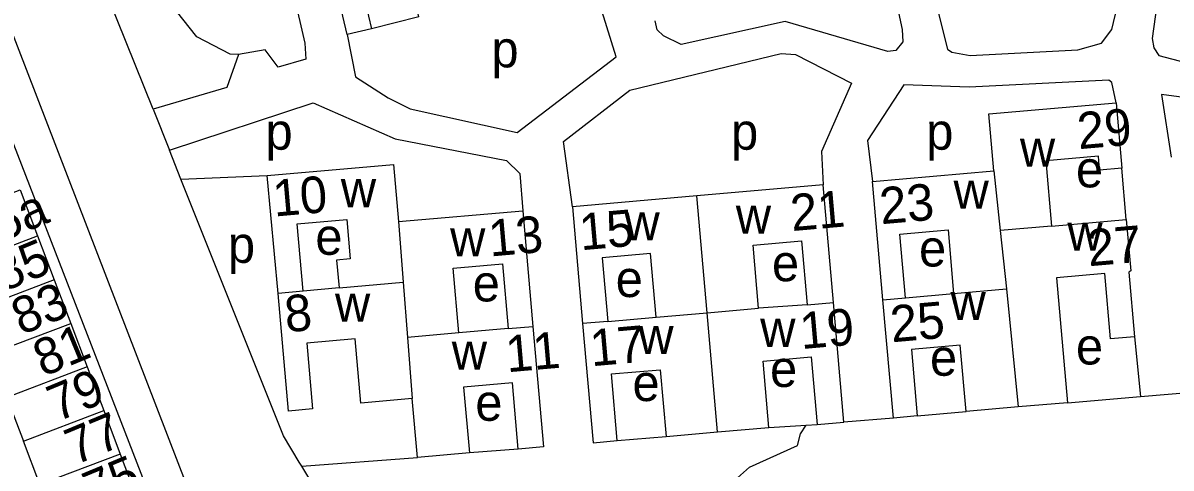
# Model space of a CAD drawing. Extents: x 163026 to 166241, y 382475 to 384501.
# Drawn here: x 164035.2 to 164160.9, y 383924.1 to 383972.8 of the extents above; entities that cross this region are included whole.
import ezdxf

# ---------------------------------------------------------------- set-up
doc = ezdxf.new("R2010")
doc.units = 0
for name, color, linetype in [('BLT_Basislijn', 7, 'Continuous'), ('BLT_Bebouwing', 7, 'Continuous'), ('BLT_Centroide', 7, 'Continuous'), ('BLT_Huisnummer', 7, 'Continuous'), ('BLT_Huisnummer_zonder_bebouwing', 7, 'Continuous'), ('BLT_Onderverdeling_panden', 7, 'Continuous'), ('BLT_Plantopo', 7, 'Continuous')]:
    doc.layers.add(name, color=color, linetype=linetype)

msp = doc.modelspace()

# ---------------------------------------------------------------- linework, layer by layer
at = {"layer": 'BLT_Basislijn'}
for p, q in [((164049.42, 383963.37), (164035.08, 383999.11)), ((164022.75, 383988.85), (164053.37, 383909.9)), ((164078.53, 383973.47), (164073.35, 383972.16)), ((164049.42, 383963.37), (164051.21, 383958.88)), ((164052.46, 383955.73), (164051.21, 383958.88)), ((164156.03, 383951.3), (164155.55, 383956.92)), ((164052.46, 383955.73), (164061.91, 383956.11)), ((164156.94, 383938.47), (164157.59, 383931.93)), ((164149.58, 383931.26), (164157.59, 383931.93)), ((164157.59, 383931.93), (164163.21, 383932.4)), ((164130.52, 383929.58), (164125.09, 383929.14)), ((164133.14, 383929.81), (164138.48, 383930.31)), ((164116.88, 383928.55), (164120.98, 383928.81)), ((164120.98, 383928.81), (164122.18, 383928.89)), ((164100.27, 383927.11), (164105.62, 383927.57)), ((164089.42, 383926.19), (164084.07, 383925.77)), ((164065.72, 383924.31), (164078.39, 383925.28)), ((164067.36, 383921.59), (164065.72, 383924.31))]:
    msp.add_line(p, q, dxfattribs=at)
for points in [[(163951.25, 383989.73), (163966.03, 383997.1), (164006.98, 384012.75), (164008.16, 384013.54), (164010.07, 384016.33), (164013.42, 384017.21), (164016.7, 384016.16), (164017.72, 384015.36), (164020.53, 384011.89), (164021.01, 384009.61), (164020.21, 384007.33), (164053.12, 383922.18), (164053.94, 383920.34), (164056.04, 383918.89), (164056.89, 383917.77), (164057.24, 383913.87), (164056.6, 383912.2), (164054.53, 383910.44), (164053.37, 383909.9)], [(164058.79, 383969.36), (164057.88, 383969.4), (164054.23, 383971.3), (164051.98, 383974.11), (164050.8, 383976.99), (164050.48, 383978.74), (164048.71, 383979.7), (164045.77, 383981.99), (164044.33, 383985.4), (164044.28, 383989.35), (164044.65, 383991.49), (164046.77, 383994.51), (164048.13, 383995.84), (164048.89, 383997.21)], [(164048.89, 383997.21), (164053.35, 383996.63), (164056.28, 383995.79), (164060.27, 383995.54), (164066.06, 383970.61), (164066.16, 383968.83), (164063.14, 383967.97), (164061.7, 383969.85), (164058.79, 383969.36)], [(164134.02, 383979.72), (164136.44, 383969.95), (164136.92, 383969.6), (164138.92, 383969.24), (164150.74, 383969.86), (164153.32, 383970.6), (164154.45, 383972.11), (164156.43, 383980.36), (164159.86, 383983.27), (164159.41, 383985.93)], [(164178.9, 383982.68), (164164.74, 383980.75), (164159.75, 383977.45), (164158.88, 383971.12), (164159.06, 383970.07), (164159.61, 383969.24), (164172.13, 383965.98), (164191.71, 383969.68), (164198.58, 383975.05), (164199, 383975.87), (164189.34, 383987), (164188.39, 383986.77), (164180.9, 383982.95), (164178.9, 383982.68)], [(164129.99, 383979.08), (164131.5, 383972.11), (164131.56, 383970.74), (164130.8, 383969.79), (164129.9, 383969.68), (164118.67, 383972.96), (164107.28, 383970.44), (164105.34, 383971.39), (164104.66, 383972.07), (164104.43, 383973.05)], [(164070.7, 383971.54), (164071.58, 383966.92), (164075.17, 383964.62), (164077.57, 383963.4), (164089.3, 383960.83), (164100.15, 383969.09), (164097.4, 383977.93)], [(164095.36, 383952.68), (164094.37, 383959.84), (164101.64, 383965.47), (164118.22, 383969.48), (164119.8, 383969.36), (164125.92, 383966.22), (164122.65, 383958.76), (164122.82, 383955.09)], [(164058.79, 383969.36), (164057.49, 383965.74), (164049.42, 383963.37)], [(164154.92, 383964.08), (164154.45, 383966.31), (164154.11, 383966.54), (164138.81, 383965.78), (164131.66, 383966.03), (164127.67, 383959.94), (164128.25, 383955.46)], [(164188.27, 383960.53), (164187.37, 383965.26), (164173.73, 383963.11), (164159.88, 383964.97), (164160.96, 383958.14)], [(164051.21, 383958.88), (164066.96, 383964.07), (164075.95, 383960.12), (164088.15, 383957.77), (164089.59, 383956.34), (164089.92, 383952.27)], [(164065.72, 383924.31), (164065.44, 383924.77), (164063.7, 383927.62), (164052.46, 383955.73)], [(164107.14, 383912.52), (164108.27, 383912.46), (164109.3, 383912.76), (164109.69, 383915.87), (164110.27, 383917.81), (164111.77, 383920.68), (164113.46, 383923.02), (164114.77, 383924.21), (164120.02, 383926.57), (164120.35, 383927.86), (164120.98, 383928.81)]]:
    msp.add_lwpolyline(points, dxfattribs=at)
at = {"layer": 'BLT_Bebouwing'}
for p, q in [((164070.7, 383971.54), (164067.72, 383984.16)), ((164073.35, 383972.16), (164070.7, 383971.54)), ((164154.92, 383964.08), (164155.55, 383956.92)), ((164063.14, 383943.21), (164061.91, 383956.11)), ((164128.25, 383955.46), (164141.51, 383956.62)), ((164122.82, 383955.09), (164108.99, 383953.88)), ((164123.95, 383942.22), (164122.82, 383955.09)), ((164129.38, 383942.52), (164128.25, 383955.46)), ((164108.99, 383953.88), (164095.36, 383952.68)), ((164076.32, 383951.08), (164089.92, 383952.27)), ((164089.92, 383952.27), (164091.02, 383939.6)), ((164095.36, 383952.68), (164096.48, 383939.91)), ((164147.85, 383950.59), (164156.03, 383951.3)), ((164069.79, 383943.81), (164065.87, 383943.46)), ((164131.84, 383942.73), (164137.12, 383943.19)), ((164121.07, 383941.97), (164115.76, 383941.6)), ((164125.09, 383929.14), (164123.95, 383942.22)), ((164130.52, 383929.58), (164129.38, 383942.52)), ((164099.23, 383940.15), (164104.53, 383940.61)), ((164088.32, 383939.37), (164082.91, 383938.89)), ((164078.39, 383925.28), (164077.82, 383931.7)), ((164144.19, 383930.81), (164138.48, 383930.31)), ((164149.58, 383931.26), (164144.19, 383930.81)), ((164133.14, 383929.81), (164130.52, 383929.58)), ((164105.62, 383927.57), (164111.25, 383928.06)), ((164111.25, 383928.06), (164116.88, 383928.55)), ((164122.18, 383928.89), (164125.09, 383929.14)), ((164084.07, 383925.77), (164078.39, 383925.28))]:
    msp.add_line(p, q, dxfattribs=at)
for points in [[(164078.53, 383973.47), (164076.91, 383980.36), (164071.71, 383979.13), (164073.35, 383972.16)], [(164141.51, 383956.62), (164140.96, 383962.86), (164154.92, 383964.08)], [(164155.55, 383956.92), (164153.11, 383956.71), (164152.98, 383958.23), (164147.23, 383957.72), (164147.85, 383950.59)], [(164061.91, 383956.11), (164075.77, 383957.32), (164076.32, 383951.08)], [(164065.87, 383943.46), (164065.22, 383950.83), (164070.63, 383951.3), (164071.01, 383947), (164069.52, 383946.87), (164069.79, 383943.81)], [(164156.03, 383951.3), (164156.52, 383945.68), (164156.33, 383945.54), (164156.94, 383938.47)], [(164131.84, 383942.73), (164131.23, 383949.7), (164136.51, 383950.16), (164137.12, 383943.19)], [(164115.76, 383941.6), (164115.16, 383948.5), (164120.45, 383948.97), (164121.07, 383941.97)], [(164104.53, 383940.61), (164103.92, 383947.57), (164098.62, 383947.1), (164099.23, 383940.15)], [(164082.91, 383938.89), (164082.29, 383945.97), (164087.7, 383946.44), (164088.32, 383939.37)], [(164156.94, 383938.47), (164154.31, 383938.24), (164153.68, 383945.39), (164148.38, 383944.92), (164149.58, 383931.26)], [(164077.82, 383931.7), (164072.18, 383931.21), (164071.56, 383938.24), (164066.26, 383937.77), (164066.89, 383930.57), (164064.26, 383930.34), (164063.14, 383943.21)], [(164091.02, 383939.6), (164092.18, 383926.43), (164089.42, 383926.19)], [(164096.48, 383939.91), (164097.62, 383926.88), (164100.27, 383927.11)], [(164138.48, 383930.31), (164137.85, 383937.54), (164132.5, 383937.08), (164133.14, 383929.81)], [(164116.88, 383928.55), (164116.25, 383935.82), (164121.53, 383936.29), (164122.18, 383928.89)], [(164100.27, 383927.11), (164099.63, 383934.4), (164104.98, 383934.87), (164105.62, 383927.57)], [(164089.42, 383926.19), (164088.78, 383933.44), (164083.44, 383932.97), (164084.07, 383925.77)]]:
    msp.add_lwpolyline(points, dxfattribs=at)
at = {"layer": 'BLT_Onderverdeling_panden'}
for p, q in [((164141.51, 383956.62), (164142.22, 383950.1)), ((164110.11, 383941.1), (164108.99, 383953.88)), ((164076.32, 383951.08), (164076.83, 383944.45)), ((164147.85, 383950.59), (164142.22, 383950.1)), ((164142.22, 383950.1), (164142.92, 383943.7)), ((164069.79, 383943.81), (164076.83, 383944.45)), ((164076.83, 383944.45), (164077.3, 383938.4)), ((164065.87, 383943.46), (164063.14, 383943.21)), ((164137.12, 383943.19), (164142.92, 383943.7)), ((164142.92, 383943.7), (164144.19, 383930.81)), ((164121.07, 383941.97), (164123.95, 383942.22)), ((164129.38, 383942.52), (164131.84, 383942.73)), ((164104.53, 383940.61), (164110.11, 383941.1)), ((164110.11, 383941.1), (164115.76, 383941.6)), ((164111.25, 383928.06), (164110.11, 383941.1)), ((164088.32, 383939.37), (164091.02, 383939.6)), ((164099.23, 383940.15), (164096.48, 383939.91)), ((164082.91, 383938.89), (164077.3, 383938.4)), ((164077.3, 383938.4), (164077.82, 383931.7))]:
    msp.add_line(p, q, dxfattribs=at)
at = {"layer": 'BLT_Plantopo'}
for p, q in [((164027.96, 383946.16), (164036.77, 383949.5)), ((164036.77, 383949.5), (164038.59, 383944.71)), ((164038.59, 383944.71), (164029.78, 383941.36)), ((164038.59, 383944.69), (164040.4, 383939.94)), ((164031.59, 383936.6), (164040.4, 383939.94)), ((164040.4, 383939.94), (164042.2, 383935.17)), ((164042.2, 383935.17), (164033.4, 383931.83)), ((164042.2, 383935.17), (164044.02, 383930.39)), ((164033.4, 383931.83), (164035.21, 383927.05)), ((164035.21, 383927.05), (164044.02, 383930.39)), ((164044.02, 383930.39), (164045.82, 383925.64)), ((164037.01, 383922.3), (164035.21, 383927.05)), ((164045.82, 383925.64), (164037.01, 383922.3)), ((164045.82, 383925.64), (164047.63, 383920.86))]:
    msp.add_line(p, q, dxfattribs=at)
msp.add_lwpolyline([(164027.96, 383946.16), (164026.05, 383951.21), (164034.86, 383954.55), (164036.77, 383949.5)], dxfattribs=at)

# ---------------------------------------------------------------- texts
at = {"layer": 'BLT_Centroide'}
for s, p in [('p', (164086.49, 383967.95)), ('p', (164061.74, 383958.94)), ('p', (164112.74, 383958.94)), ('p', (164134.12, 383958.94)), ('w', (164144.38, 383957.09)), ('e', (164150.52, 383954.82)), ('w', (164069.99, 383952.65)), ('w', (164137.11, 383952.49)), ('w', (164101.06, 383949.02)), ('w', (164113.26, 383949.75)), ('w', (164149.58, 383947.89)), ('p', (164057.62, 383946.56)), ('e', (164067.2, 383947.44)), ('w', (164081.96, 383947.27)), ('e', (164133.33, 383946.16)), ('e', (164117.22, 383944.55)), ('e', (164100.1, 383942.82)), ('e', (164084.44, 383942.34)), ('w', (164069.35, 383940.13)), ('w', (164136.78, 383940.3)), ('w', (164102.58, 383936.59)), ('w', (164115.93, 383937.37)), ('e', (164150.52, 383935.44)), ('w', (164082.14, 383934.88)), ('e', (164134.53, 383934.21)), ('e', (164117.01, 383932.98)), ('e', (164101.94, 383931.44)), ('e', (164084.72, 383929.28))]:
    msp.add_text(s, height=4, dxfattribs=at).set_placement(p)
at = {"layer": 'BLT_Huisnummer'}
for s, rotation, p in [('29', 5.0084, (164150.83, 383958.99)), ('10', 4.9985, (164062.71, 383951.62)), ('21', 5.009, (164119.41, 383950.03)), ('23', 5.0046, (164129.18, 383950.78)), ('15', 5.0052, (164096.29, 383947.93)), ('13', 5.0045, (164086.34, 383947.25)), ('27', 5.0024, (164151.93, 383946.18)), ('8', 5.0096, (164064, 383938.96)), ('25', 5.0058, (164130.35, 383937.86)), ('19', 5.0058, (164120.44, 383937.12)), ('17', 4.9975, (164097.46, 383935.24)), ('11', 5.0068, (164088.22, 383934.58))]:
    msp.add_text(s, height=4, rotation=rotation, dxfattribs=at).set_placement(p)
at = {"layer": 'BLT_Huisnummer_zonder_bebouwing'}
for s, p in [('85a', (164030.04, 383947.67)), ('85', (164033.03, 383943.35)), ('83', (164034.99, 383938.61)), ('81', (164037.37, 383934.05)), ('79', (164038.91, 383929.13)), ('77', (164040.86, 383924.39)), ('75', (164042.84, 383919.66))]:
    msp.add_text(s, height=4, rotation=22.4972, dxfattribs=at).set_placement(p)

doc.saveas('drawing.dxf')
